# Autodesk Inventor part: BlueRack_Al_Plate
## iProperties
Shininess: 64.0
Length Units: 11272
Angle Units: 11279
Time Units: 11290
Mass Units: 11286
Length Display Precision: 3
Angle Display Precision: 2
Compacted: True
Part Number: BlueRack_Al_Plate
Document SubType Name: Modeling
Created: 2004-12
Designer: John Blackburn
Material: Aluminum-6061
Manufacturer: Standard
Standards Organization: Custom
Density: 0.0
Volumn: 0.0
Area: 0.0
PropertySet Name: Model Information
Control State: 0
Master: False
Checked Out: False
Author: John Blackburn
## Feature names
1. Extrusion1
